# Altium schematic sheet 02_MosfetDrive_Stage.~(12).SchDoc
size A4; SheetNumber: 2; SheetTotal: 2
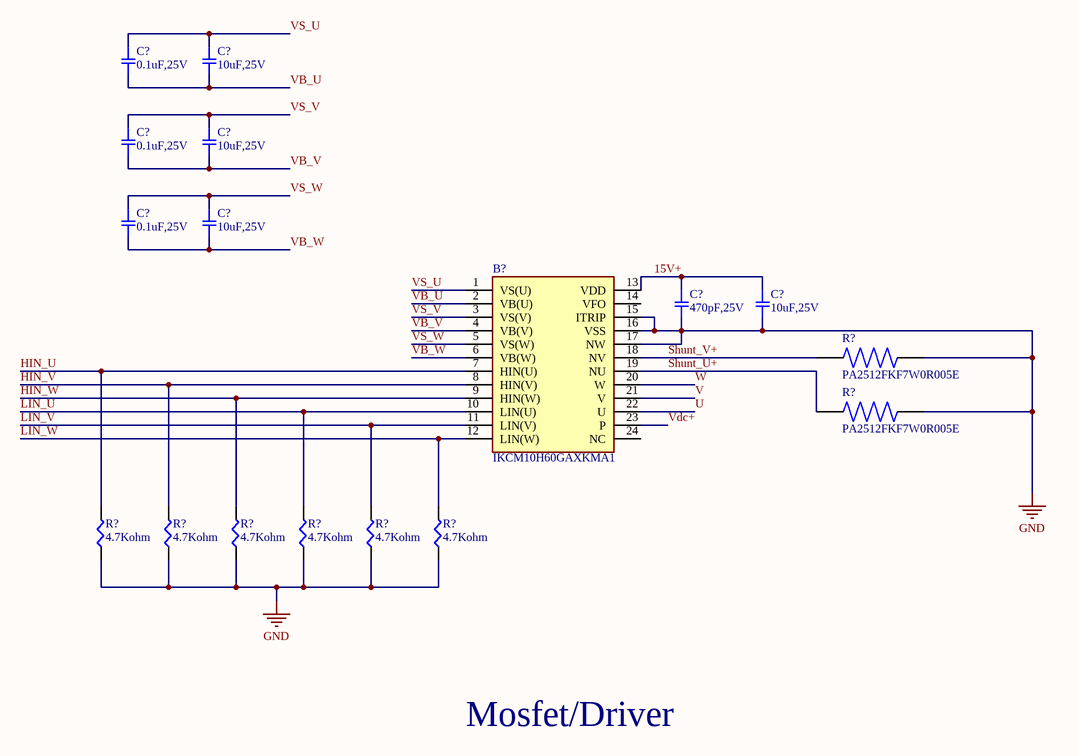
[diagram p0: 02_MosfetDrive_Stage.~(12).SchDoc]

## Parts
(Parts that share a designator on the sheet are numbered #1, #2 ... from top to bottom, then left to right.)
B?  IKCM10H60GAXKMA1  [997_IKCM10H60GAXKMA1]
C?#1  0.1uF,25V  [001_SMD-1206]
C?#2  10uF,25V  [001_SMD-1206]
C?#3  0.1uF,25V  [001_SMD-1206]
C?#4  10uF,25V  [001_SMD-1206]
C?#5  0.1uF,25V  [001_SMD-1206]
C?#6  10uF,25V  [001_SMD-1206]
C?#7  470pF,25V  [006_SMD_0605]
C?#8  10uF,25V  [006_SMD_0605]
R?#1  PA2512FKF7W0R005E  [097_PA2512FKF7W0R005E]
R?#2  PA2512FKF7W0R005E  [097_PA2512FKF7W0R005E]
R?#3  4.7Kohm  [001_SMD-1206]
R?#4  4.7Kohm  [001_SMD-1206]
R?#5  4.7Kohm  [001_SMD-1206]
R?#6  4.7Kohm  [001_SMD-1206]
R?#7  4.7Kohm  [001_SMD-1206]
R?#8  4.7Kohm  [001_SMD-1206]

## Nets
GND: B?.15(ITRIP) B?.16(VSS) B?.17(NW) C?#7.2 C?#8.2 R?#1.2 R?#2.2 R?#3.1 R?#4.1 R?#5.1 R?#6.1 R?#7.1 R?#8.1
15V+: B?.13(VDD) C?#7.1 C?#8.1
HIN_U: B?.7(HIN(U)) R?#3.2
HIN_V: B?.8(HIN(V)) R?#4.2
HIN_W: B?.9(HIN(W)) R?#5.2
LIN_U: B?.10(LIN(U)) R?#6.2
LIN_V: B?.11(LIN(V)) R?#7.2
LIN_W: B?.12(LIN(W)) R?#8.2
Shunt_U+: B?.19(NU) R?#2.1
Shunt_V+: B?.18(NV) R?#1.1
U: B?.22(U)
V: B?.21(V)
VB_U: B?.2(VB(U)) C?#1.2 C?#2.2
VB_V: B?.4(VB(V)) C?#3.2 C?#4.2
VB_W: B?.6(VB(W)) C?#5.2 C?#6.2
Vdc+: B?.23(P)
VS_U: B?.1(VS(U)) C?#1.1 C?#2.1
VS_V: B?.3(VS(V)) C?#3.1 C?#4.1
VS_W: B?.5(VS(W)) C?#5.1 C?#6.1
W: B?.20(W)

Not connected (* = marked no-connect by the designer): B? 14(VFO) 24(NC)

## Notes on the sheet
- Mosfet/Driver

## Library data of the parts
B? = IKCM10H60GAXKMA1: Intelligent Power Module 3-Ph 600V 10A; Manufacturer_Name: Infineon; Geometry.Height: 5.6mm
C?#1-C?#6 = C_1206_Template: CAP CER 1206; Part Number: GC321AD72E103KX01D; Manufacturer: Murata Electronics North America; Factory Stock: 0; Unit Price (USD): 0.3; Minimum Quantity: 1; Value: 10000pF; Tolerance: ±10%; Voltage: 250V; Temperature Coefficient: X7T
C?#7 C?#8 = C_0605_Template: CAP CER 0605; Part Number: GC321AD72E103KX01D; Manufacturer: Murata Electronics North America; Factory Stock: 0; Unit Price (USD): 0.3; Minimum Quantity: 1; Value: 10000pF; Tolerance: ±10%; Voltage: 250V; Temperature Coefficient: X7T
R?#1 R?#2 = PA2512FKF7W0R005E: 5 mΩ, 2 W, ±1% current-sense shunt resistor, 2512 (6332 metric) SMD package, low-resistance metal-element construction.; MF: Bourns; MP: CRF2512-FZ-R005ELF
R?#3-R?#8 = R_1206_Template: RES SMD 1206; Part Number: ERJ-8BQF1R0V; Manufacturer: Panasonic Electronic Components; Factory Stock: 0; Unit Price (USD): 0.05778; @ qty: 1500; Minimum Quantity: 1; Value: 1; Tolerance: ±1%; Power (Watts): 0.5W, 1/2W; Temperature Coefficient: ±200ppm/°C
